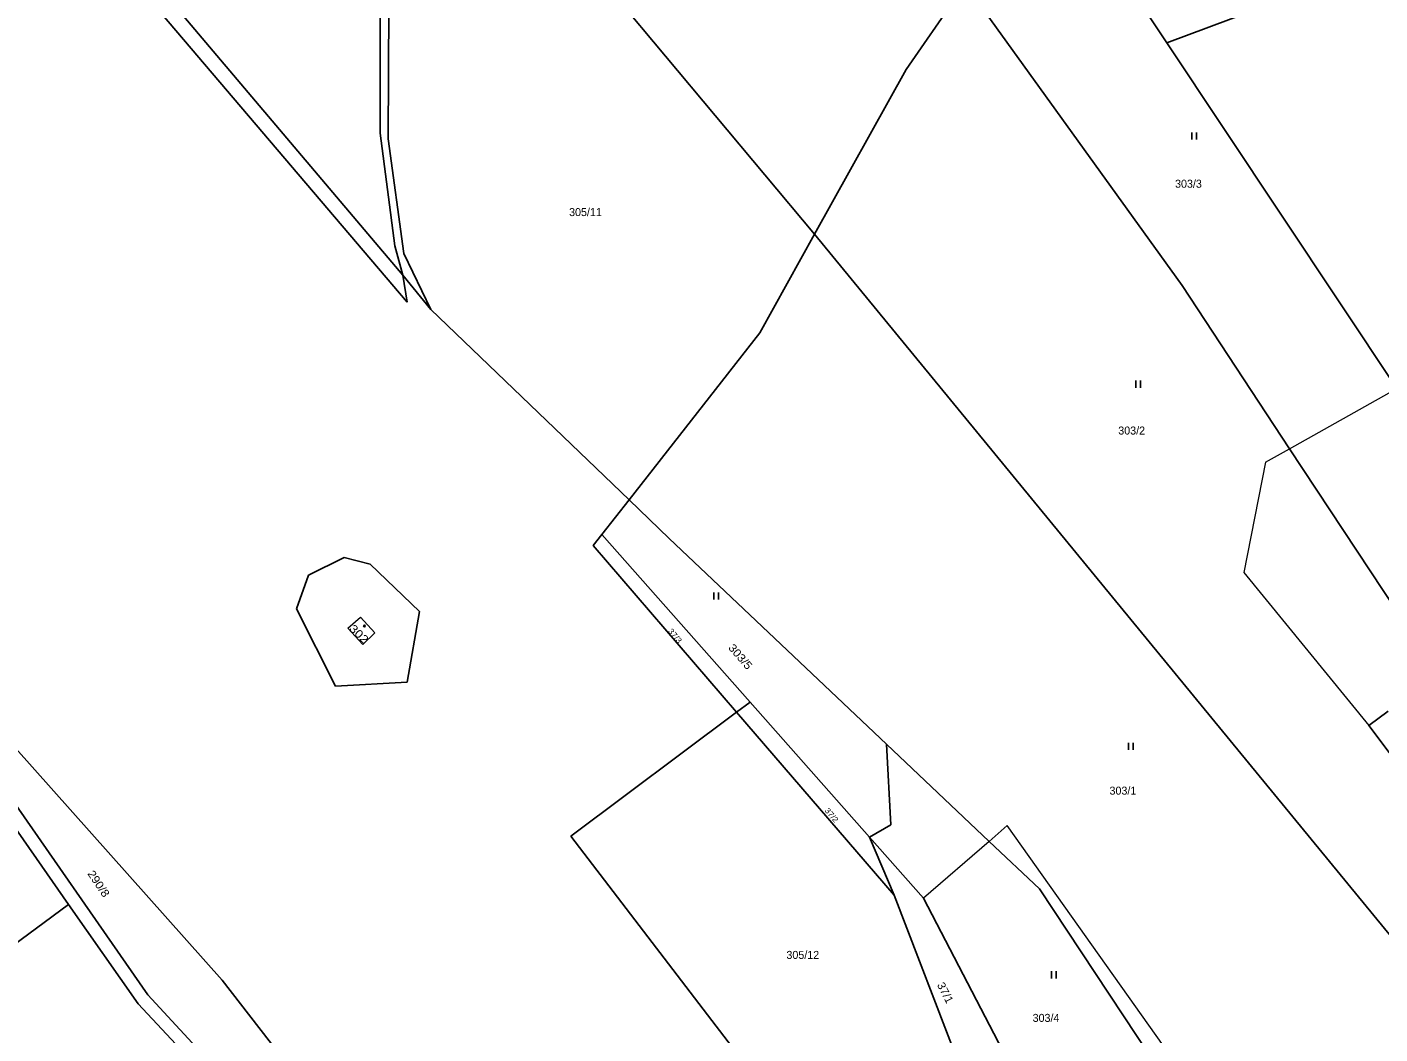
# Model space of a CAD drawing. Extents: x -504006 to -501322, y -1128098 to -1124665.
# Drawn here: x -503112.2 to -502824.9, y -1126516.9 to -1126303.1 of the extents above; entities that cross this region are included whole.
import ezdxf
from ezdxf.enums import TextEntityAlignment as Align

# ---------------------------------------------------------------- set-up
doc = ezdxf.new("R2010")
doc.units = 0
doc.header["$LTSCALE"] = 0.68
for name, color, linetype, lineweight in [('1', 7, 'Continuous', 25), ('3', 7, 'Continuous', 25), ('4', 7, 'Continuous', 13), ('5', 7, 'Continuous', 25)]:
    doc.layers.add(name, color=color, linetype=linetype, lineweight=lineweight)
doc.layers.add('2', color=7, linetype='Continuous')

msp = doc.modelspace()

# ---------------------------------------------------------------- linework, layer by layer
at = {"layer": '1'}
for p, q in [((-503165.99, -1126198.03), (-503032.36, -1126355.77)), ((-503169, -1126199.97), (-503031.45, -1126361.5)), ((-503030.18, -1126245.26), (-502944.94, -1126347.11)), ((-502898.63, -1126263.67), (-502870.11, -1126306.48)), ((-503037.21, -1126325.65), (-503037.21, -1126292.62)), ((-502912.93, -1126294.01), (-502925.46, -1126312.1)), ((-502912.93, -1126294.01), (-502866.89, -1126357.98)), ((-503035.39, -1126298.61), (-503035.5, -1126326.86)), ((-502870.11, -1126306.48), (-502852.3, -1126299.81)), ((-502821.24, -1126379.86), (-502870.11, -1126306.48)), ((-502925.46, -1126312.1), (-502944.94, -1126347.11)), ((-503034.08, -1126349.6), (-503037.21, -1126325.65)), ((-503035.5, -1126326.86), (-503032.16, -1126351.19)), ((-502944.94, -1126347.11), (-502956.57, -1126368.01)), ((-502944.94, -1126347.11), (-502816.86, -1126503.09)), ((-503032.36, -1126355.77), (-503034.08, -1126349.6)), ((-503032.16, -1126351.19), (-503026.44, -1126363.08)), ((-503031.45, -1126361.5), (-503032.36, -1126355.77)), ((-503026.44, -1126363.08), (-503032.36, -1126355.77)), ((-502866.89, -1126357.98), (-502844.04, -1126392.64)), ((-503026.44, -1126363.08), (-502984.35, -1126403.48)), ((-502956.57, -1126368.01), (-502984.35, -1126403.48)), ((-502844.04, -1126392.64), (-502810.65, -1126443.26)), ((-502984.35, -1126403.48), (-502990.12, -1126410.84)), ((-502984.35, -1126403.48), (-502975.81, -1126411.68)), ((-502991.97, -1126413.2), (-502990.12, -1126410.84)), ((-502990.12, -1126410.84), (-502958.64, -1126446.43)), ((-502975.81, -1126411.68), (-502929.69, -1126455.34)), ((-503152.41, -1126413.95), (-503086.56, -1126508.57)), ((-503070.75, -1126505.48), (-503152.41, -1126413.95)), ((-502961.5, -1126448.57), (-502991.97, -1126413.2)), ((-503052.39, -1126419.49), (-503044.85, -1126415.73)), ((-503044.85, -1126415.73), (-503039.32, -1126417.12)), ((-503039.32, -1126417.12), (-503028.83, -1126427.17)), ((-503054.97, -1126426.67), (-503052.39, -1126419.49)), ((-503046.68, -1126443.06), (-503054.97, -1126426.67)), ((-503028.83, -1126427.17), (-503031.48, -1126442.18)), ((-503031.48, -1126442.18), (-503046.68, -1126443.06)), ((-502961.5, -1126448.57), (-502958.64, -1126446.43)), ((-502958.64, -1126446.43), (-502933.28, -1126475.09)), ((-502996.74, -1126474.92), (-502961.5, -1126448.57)), ((-502928, -1126487.44), (-502961.5, -1126448.57)), ((-502827.19, -1126451.44), (-502823.08, -1126448.36)), ((-502807.45, -1126477.77), (-502827.19, -1126451.44)), ((-502929.69, -1126455.34), (-502907.87, -1126476)), ((-502928.74, -1126472.49), (-502929.69, -1126455.34)), ((-503126.79, -1126455.95), (-503103.37, -1126489.4)), ((-502933.28, -1126475.09), (-502928.74, -1126472.49)), ((-502943.13, -1126544.82), (-502996.74, -1126474.92)), ((-502928, -1126487.44), (-502933.28, -1126475.09)), ((-502933.28, -1126475.09), (-502921.83, -1126488.04)), ((-502907.87, -1126476), (-502897.2, -1126486.11)), ((-502897.2, -1126486.11), (-502873.53, -1126521.82)), ((-503103.37, -1126489.4), (-503306.91, -1126639.7)), ((-503103.37, -1126489.4), (-503088.6, -1126510.51)), ((-502912.7, -1126527.24), (-502928, -1126487.44)), ((-502921.83, -1126488.04), (-502904.06, -1126522.24)), ((-503019.46, -1126571.46), (-503070.75, -1126505.48)), ((-503086.56, -1126508.57), (-503066.84, -1126529.83)), ((-503088.6, -1126510.51), (-503070.09, -1126530.2))]:
    msp.add_line(p, q, dxfattribs=at)
at = {"layer": '3'}
for p, q in [((-502864.821, -1126326.98), (-502864.821, -1126325.48)), ((-502863.82, -1126326.98), (-502863.82, -1126325.48)), ((-502876.691, -1126379.69), (-502876.691, -1126378.19)), ((-502875.69, -1126379.69), (-502875.69, -1126378.19)), ((-502966.351, -1126424.65), (-502966.351, -1126423.15)), ((-502965.35, -1126424.65), (-502965.35, -1126423.15)), ((-502878.271, -1126456.57), (-502878.271, -1126455.07)), ((-502877.27, -1126456.57), (-502877.27, -1126455.07)), ((-502894.651, -1126505.09), (-502894.651, -1126503.59)), ((-502893.65, -1126505.09), (-502893.65, -1126503.59))]:
    msp.add_line(p, q, dxfattribs=at)
at = {"layer": '4'}
for p, q in [((-502844.04, -1126392.64), (-502821.77, -1126380.16)), ((-502849.17, -1126395.51), (-502844.04, -1126392.64)), ((-502849.17, -1126395.51), (-502853.8, -1126418.89)), ((-502853.8, -1126418.89), (-502827.19, -1126451.44)), ((-503044.09, -1126430.71), (-503041.4, -1126428.41)), ((-503041.4, -1126428.41), (-503038.34, -1126431.74)), ((-503040.85, -1126434.21), (-503044.09, -1126430.71)), ((-503038.34, -1126431.74), (-503040.85, -1126434.21)), ((-502904, -1126472.67), (-502907.87, -1126476)), ((-502870.85, -1126519.42), (-502904, -1126472.67)), ((-502907.87, -1126476), (-502921.83, -1126488.04))]:
    msp.add_line(p, q, dxfattribs=at)
at = {"layer": '5'}
msp.add_circle((-503040.5368, -1126430.2692), 0.175, dxfattribs=at)

# ---------------------------------------------------------------- texts
at = {"layer": '2'}
for s, p in [('303/3', (-502865.53, -1126337.235)), ('305/11', (-502993.6, -1126343.255)), ('303/2', (-502877.59, -1126389.635)), ('303/1', (-502879.45, -1126466.085)), ('305/12', (-502947.44, -1126500.965)), ('303/4', (-502895.78, -1126514.335))]:
    msp.add_text(s, height=1.7, dxfattribs=at).set_placement(p, align=Align.CENTER)
for s, height, rotation, width, p in [('302', 1.7, 316, 1.2, (-503042.2845, -1126432.5756)), ('37/3', 1.2, 310, 1.1, (-502975.0242, -1126432.7493)), ('303/5', 1.7, 311, 1.1, (-502961.3335, -1126437.3524)), ('37/2', 1.2, 310, 1.1, (-502941.7742, -1126470.8193)), ('290/8', 1.7, 304, 1.1, (-503097.6989, -1126485.4692)), ('37/1', 1.7, 297, 1.05, (-502917.9286, -1126508.5286))]:
    msp.add_text(s, height=height, rotation=rotation, dxfattribs=dict(at, width=width)).set_placement(p, align=Align.CENTER)

doc.saveas('drawing.dxf')
